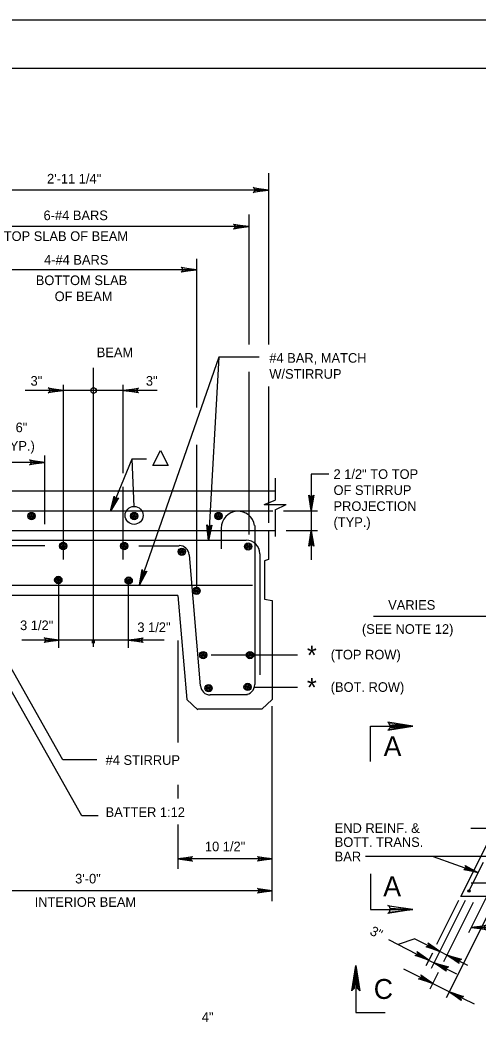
# Model space of a CAD drawing. Extents: x 642009 to 642864, y 298232 to 300014.
# Drawn here: x 642423.1 to 642566, y 299702.6 to 300013.8 of the extents above; entities that cross this region are included whole.
import ezdxf

# ---------------------------------------------------------------- set-up
doc = ezdxf.new("R2010")
doc.units = 0
for name, color, linetype in [('1', 7, 'Continuous'), ('2', 7, 'Continuous'), ('PLT-BNDY', 7, 'Continuous')]:
    doc.layers.add(name, color=color, linetype=linetype)

msp = doc.modelspace()

# ---------------------------------------------------------------- linework, layer by layer
at = {"layer": '1'}
msp.add_line((642552.01, 299752.72), (642565.95, 299747.74), dxfattribs=at)
for points in [[(642496.11, 299961.31), (642496.28, 299960.98), (642500.65, 299960.74), (642496.11, 299961.31), (642495.87, 299961.51), (642500.65, 299960.74), (642496.28, 299960.52), (642496.12, 299960.2), (642500.65, 299960.74), (642495.87, 299959.98), (642496.12, 299960.2)], [(642489.92, 299949.87), (642490.09, 299949.54), (642494.46, 299949.3), (642489.92, 299949.87), (642489.69, 299950.07), (642494.46, 299949.3), (642490.09, 299949.08), (642489.93, 299948.76), (642494.46, 299949.3), (642489.69, 299948.54), (642489.93, 299948.76)], [(642473.61, 299936.41), (642473.78, 299936.08), (642478.15, 299935.84), (642473.61, 299936.41), (642473.37, 299936.61), (642478.15, 299935.84), (642473.78, 299935.62), (642473.62, 299935.3), (642478.15, 299935.84), (642473.37, 299935.08), (642473.62, 299935.3)], [(642432.17, 299898.75), (642432.34, 299898.43), (642436.71, 299898.18), (642432.17, 299898.75), (642431.94, 299898.95), (642436.71, 299898.18), (642432.34, 299897.97), (642432.18, 299897.64), (642436.71, 299898.18), (642431.94, 299897.43), (642432.18, 299897.64)], [(642459.81, 299897.61), (642459.64, 299897.94), (642455.27, 299898.18), (642459.81, 299897.61), (642460.05, 299897.42), (642455.27, 299898.18), (642459.64, 299898.4), (642459.8, 299898.73), (642455.27, 299898.18), (642460.05, 299898.94), (642459.8, 299898.73)], [(642426.34, 299876.28), (642426.51, 299875.95), (642430.88, 299875.71), (642426.34, 299876.28), (642426.1, 299876.48), (642430.88, 299875.71), (642426.51, 299875.49), (642426.35, 299875.17), (642430.88, 299875.71), (642426.1, 299874.95), (642426.35, 299875.17)], [(642453.6, 299864.47), (642453.23, 299864.44), (642451.36, 299860.48), (642453.6, 299864.47), (642453.87, 299864.61), (642451.36, 299860.48), (642452.81, 299864.61), (642452.57, 299864.88), (642451.36, 299860.48), (642452.46, 299865.19), (642452.57, 299864.88)], [(642514.53, 299865.24), (642514.21, 299865.07), (642513.96, 299860.7), (642514.53, 299865.24), (642514.73, 299865.47), (642513.96, 299860.7), (642513.75, 299865.07), (642513.42, 299865.22), (642513.96, 299860.7), (642513.21, 299865.47), (642513.42, 299865.22)], [(642482.74, 299855.89), (642482.4, 299855.74), (642481.91, 299851.38), (642482.74, 299855.89), (642482.95, 299856.11), (642481.91, 299851.38), (642481.94, 299855.76), (642481.63, 299855.93), (642481.91, 299851.38), (642481.42, 299856.19), (642481.63, 299855.93)], [(642513.39, 299849.85), (642513.72, 299850.02), (642513.96, 299854.39), (642513.39, 299849.85), (642513.2, 299849.61), (642513.96, 299854.39), (642514.18, 299850.02), (642514.51, 299849.86), (642513.96, 299854.39), (642514.72, 299849.61), (642514.51, 299849.86)], [(642462.37, 299841.61), (642462, 299841.56), (642460.33, 299837.51), (642462.37, 299841.61), (642462.63, 299841.77), (642460.33, 299837.51), (642461.57, 299841.71), (642461.31, 299841.97), (642460.33, 299837.51), (642461.19, 299842.27), (642461.31, 299841.97)]]:
    msp.add_lwpolyline(points, dxfattribs=at)
msp.add_lwpolyline([(642464.5, 299874.7), (642466.91, 299879.39), (642469.32, 299874.7)], close=True, dxfattribs=at)
msp.add_circle((642458.7, 299859.18), 2.8, dxfattribs=at)
at = {"layer": '2'}
for p, q in [((642048.66, 299998.82), (642834.66, 299998.82)), ((642500.65, 299965.98), (642500.65, 299912.51)), ((642500.65, 299960.74), (642391.52, 299960.74)), ((642494.46, 299953.06), (642494.46, 299912.51)), ((642494.46, 299949.3), (642397.22, 299949.3)), ((642478.15, 299939.21), (642478.15, 299892.89)), ((642478.15, 299935.84), (642414.02, 299935.84)), ((642485.1, 299908.54), (642460.27, 299837.32)), ((642485.1, 299908.54), (642481.91, 299851.38)), ((642497.67, 299908.54), (642485.1, 299908.54)), ((642446.08, 299818.2), (642446.08, 299905.26)), ((642494.46, 299903.95), (642494.46, 299853.19)), ((642436.71, 299898.18), (642424.75, 299898.18)), ((642436.71, 299845.39), (642436.71, 299899.89)), ((642455.27, 299898.18), (642436.71, 299898.18)), ((642455.27, 299872.33), (642455.27, 299899.89)), ((642465.86, 299898.18), (642455.27, 299898.18)), ((642500.65, 299899.37), (642500.65, 299856.89)), ((642478.15, 299881.18), (642478.15, 299836.39)), ((642430.88, 299875.71), (642416.94, 299875.71)), ((642430.88, 299856.47), (642430.88, 299877.85)), ((642457.94, 299876.74), (642451.36, 299860.48)), ((642462.58, 299876.74), (642457.94, 299876.74)), ((642457.94, 299876.74), (642458.64, 299861.98)), ((642502.67, 299870.76), (642502.67, 299863.94)), ((642502.67, 299869.89), (642502.67, 299867.77)), ((642513.96, 299872), (642513.96, 299860.7)), ((642519.39, 299872), (642513.96, 299872)), ((642502.67, 299866.72), (642387.65, 299866.72)), ((642455.27, 299845.39), (642455.27, 299868.06)), ((642499.29, 299862.54), (642502.67, 299863.94)), ((642501.93, 299860.48), (642391.81, 299860.48)), ((642499.29, 299862.54), (642506.17, 299862.54)), ((642502.67, 299860.87), (642506.17, 299862.54)), ((642502.67, 299860.87), (642502.67, 299852.58)), ((642515.87, 299860.52), (642505.32, 299860.52)), ((642513.96, 299860.7), (642513.96, 299854.39)), ((642502.67, 299858.12), (642502.67, 299855.42)), ((642502.67, 299854.39), (642387.65, 299854.39)), ((642485.89, 299855.23), (642485.89, 299848.72)), ((642496.3, 299855.99), (642496.3, 299806.39)), ((642500.65, 299854.39), (642500.65, 299845.39)), ((642515.87, 299854.39), (642506.12, 299854.39)), ((642513.96, 299854.39), (642513.96, 299845.26)), ((642493.64, 299851.38), (642398.5, 299851.38)), ((642430.88, 299849.71), (642419.25, 299849.71)), ((642460.22, 299849.7), (642472.78, 299849.7)), ((642475.92, 299846.91), (642479.27, 299806.01)), ((642497.89, 299847.21), (642497.89, 299809.39)), ((642500.65, 299845.39), (642499.33, 299845.01)), ((642499.33, 299845.01), (642499.33, 299833.01)), ((642435.21, 299817.82), (642435.21, 299838.45)), ((642456.96, 299817.82), (642456.96, 299838.45)), ((642495.58, 299837.32), (642396.4, 299837.32)), ((642472.33, 299834.14), (642419.83, 299834.14)), ((642472.33, 299834.14), (642475.15, 299801.7)), ((642499.33, 299833.01), (642501.77, 299832.64)), ((642501.77, 299832.64), (642501.77, 299801.7)), ((642533.37, 299827.76), (642571.96, 299827.76)), ((642436.44, 299782.86), (642414.07, 299822.57)), ((642435.21, 299820.26), (642423.66, 299820.26)), ((642446.27, 299820.26), (642435.21, 299820.26)), ((642456.96, 299820.26), (642446.27, 299820.26)), ((642468.06, 299820.26), (642456.94, 299820.26)), ((642472.33, 299820.1), (642472.33, 299788.34)), ((642503.65, 299815.57), (642482.72, 299815.57)), ((642509.65, 299815.57), (642502.52, 299815.57)), ((642442.37, 299765.44), (642417.96, 299808.76)), ((642509.65, 299805.41), (642496.2, 299805.41)), ((642475.15, 299801.7), (642478.52, 299798.51)), ((642494.08, 299803.2), (642482.46, 299803.2)), ((642501.77, 299801.7), (642498.58, 299798.7)), ((642498.58, 299798.7), (642478.52, 299798.7)), ((642501.77, 299788.34), (642501.77, 299799.64)), ((642501.77, 299738.72), (642501.77, 299799.64)), ((642532.45, 299793.4), (642545.66, 299793.4)), ((642532.45, 299782.33), (642532.45, 299793.4)), ((642563.05, 299729.01), (642595.68, 299794.41)), ((642447.03, 299782.86), (642436.44, 299782.86)), ((642560.61, 299740.22), (642581.91, 299782.91)), ((642472.33, 299775.12), (642472.33, 299770.82)), ((642447.45, 299765.44), (642442.37, 299765.44)), ((642472.33, 299762.65), (642472.33, 299748.83)), ((642671.29, 299761.49), (642563.68, 299761.49)), ((642501.77, 299751.95), (642472.33, 299751.95)), ((642577.71, 299752.72), (642530.85, 299752.72)), ((642567.53, 299750.83), (642563.12, 299741.97)), ((642532.45, 299747.26), (642532.45, 299736.19)), ((642501.77, 299742.02), (642390.4, 299742.02)), ((642563.12, 299741.94), (642563.12, 299741.94)), ((642563.12, 299741.94), (642563.12, 299741.94)), ((642563.12, 299741.94), (642563.12, 299741.94)), ((642563.12, 299741.94), (642563.12, 299741.94)), ((642563.12, 299741.94), (642563.12, 299741.94)), ((642563.12, 299741.94), (642563.12, 299741.94)), ((642563.12, 299741.94), (642563.12, 299741.94)), ((642563.12, 299741.94), (642563.12, 299741.94)), ((642563.12, 299741.94), (642563.12, 299741.94)), ((642563.12, 299741.94), (642563.12, 299741.94)), ((642563.12, 299741.94), (642563.12, 299741.94)), ((642563.12, 299741.94), (642563.12, 299741.94)), ((642563.12, 299741.94), (642563.12, 299741.94)), ((642656.06, 299744.39), (642563.78, 299744.39)), ((642551.48, 299717.86), (642562.04, 299739.04)), ((642553.15, 299725.34), (642560.02, 299739.03)), ((642556.13, 299708.73), (642571.21, 299738.82)), ((642656.06, 299740.22), (642560.61, 299740.22)), ((642532.45, 299736.19), (642545.66, 299736.19)), ((642555.33, 299719.97), (642564.52, 299738.41)), ((642563.91, 299730.59), (642578.29, 299730.59)), ((642538.01, 299726.77), (642549.73, 299720.82)), ((642546.23, 299727.04), (642541.01, 299725.24)), ((642546.23, 299727.04), (642553.15, 299723.53)), ((642553.15, 299723.53), (642557.17, 299721.52)), ((642549.73, 299720.82), (642553.75, 299718.81)), ((642549.8, 299718.66), (642551.82, 299722.69)), ((642557.17, 299721.52), (642562.64, 299718.79)), ((642527.83, 299718.66), (642527.83, 299703.99)), ((642542.71, 299717.63), (642551.08, 299713.45)), ((642553.75, 299718.81), (642559.21, 299716.08)), ((642551.04, 299711.36), (642553.65, 299716.59)), ((642551.08, 299713.45), (642557.69, 299710.14)), ((642557.69, 299710.14), (642564.72, 299706.69)), ((642527.83, 299703.99), (642537.03, 299703.99))]:
    msp.add_line(p, q, dxfattribs=at)
for points in [[(642430.85, 299820.81), (642431.01, 299820.49), (642435.21, 299820.26), (642430.85, 299820.81), (642430.63, 299821), (642435.21, 299820.26), (642431.02, 299820.05), (642430.86, 299819.74), (642435.21, 299820.26), (642430.63, 299819.53), (642430.86, 299819.74)], [(642461.3, 299819.71), (642461.14, 299820.03), (642456.94, 299820.26), (642461.3, 299819.71), (642461.52, 299819.52), (642456.94, 299820.26), (642461.13, 299820.47), (642461.29, 299820.78), (642456.94, 299820.26), (642461.52, 299820.99), (642461.29, 299820.78)], [(642538.2, 299792.36), (642538.41, 299792.99), (642545.66, 299793.4), (642538.2, 299792.36), (642537.79, 299792.16), (642545.66, 299793.4), (642538.41, 299793.61), (642538.2, 299794.23), (642545.66, 299793.4), (642537.79, 299794.64), (642538.2, 299794.23)], [(642476.69, 299751.41), (642476.53, 299751.72), (642472.33, 299751.95), (642476.69, 299751.41), (642476.92, 299751.21), (642472.33, 299751.95), (642476.53, 299752.16), (642476.68, 299752.47), (642472.33, 299751.95), (642476.92, 299752.68), (642476.68, 299752.47)], [(642497.41, 299752.5), (642497.57, 299752.18), (642501.77, 299751.95), (642497.41, 299752.5), (642497.19, 299752.69), (642501.77, 299751.95), (642497.58, 299751.75), (642497.42, 299751.43), (642501.77, 299751.95), (642497.19, 299751.22), (642497.42, 299751.43)], [(642562.06, 299749.68), (642562.11, 299749.37), (642565.95, 299747.74), (642562.06, 299749.68), (642561.98, 299749.87), (642565.95, 299747.74), (642561.97, 299748.96), (642561.74, 299748.73), (642565.95, 299747.74), (642561.51, 299748.51), (642561.74, 299748.73)], [(642497.41, 299742.57), (642497.57, 299742.26), (642501.77, 299742.02), (642497.41, 299742.57), (642497.19, 299742.76), (642501.77, 299742.02), (642497.58, 299741.82), (642497.42, 299741.5), (642501.77, 299742.02), (642497.19, 299741.3), (642497.42, 299741.5)], [(642538.2, 299737.23), (642538.41, 299736.61), (642545.66, 299736.19), (642538.2, 299737.23), (642537.79, 299737.44), (642545.66, 299736.19), (642538.41, 299735.99), (642538.2, 299735.37), (642545.66, 299736.19), (642537.79, 299734.95), (642538.2, 299735.37)], [(642568.23, 299730.01), (642568.08, 299730.3), (642563.91, 299730.59), (642568.23, 299730.01), (642568.51, 299729.87), (642563.91, 299730.59), (642568.08, 299730.73), (642568.23, 299731.02), (642563.91, 299730.59), (642568.51, 299731.31), (642568.23, 299731.02)], [(642547.06, 299722.8), (642547.06, 299722.51), (642550.65, 299720.36), (642547.06, 299722.8), (642546.91, 299723.09), (642550.65, 299720.36), (642546.91, 299722.08), (642546.63, 299721.94), (642550.65, 299720.36), (642546.34, 299721.8), (642546.63, 299721.94)], [(642550.48, 299725.51), (642550.48, 299725.22), (642554.07, 299723.07), (642550.48, 299725.51), (642550.33, 299725.8), (642554.07, 299723.07), (642550.33, 299724.79), (642550.05, 299724.65), (642554.07, 299723.07), (642549.76, 299724.51), (642550.05, 299724.65)], [(642559.91, 299719.64), (642559.91, 299719.93), (642556.32, 299721.94), (642559.91, 299719.64), (642560.06, 299719.36), (642556.32, 299721.94), (642560.2, 299720.36), (642560.49, 299720.51), (642556.32, 299721.94), (642560.77, 299720.65), (642560.49, 299720.51)], [(642526.8, 299711.21), (642527.42, 299711.62), (642527.83, 299718.66), (642526.8, 299711.21), (642526.59, 299710.79), (642527.83, 299718.66), (642528.25, 299711.62), (642528.66, 299711.21), (642527.83, 299718.66), (642529.07, 299710.79), (642528.66, 299711.21)], [(642555.91, 299717.23), (642555.91, 299717.51), (642552.31, 299719.53), (642555.91, 299717.23), (642556.05, 299716.94), (642552.31, 299719.53), (642556.19, 299717.95), (642556.48, 299718.09), (642552.31, 299719.53), (642556.77, 299718.23), (642556.48, 299718.09)], [(642548.23, 299715.52), (642548.23, 299715.23), (642551.83, 299713.07), (642548.23, 299715.52), (642548.09, 299715.81), (642551.83, 299713.07), (642547.95, 299714.8), (642547.8, 299714.51), (642551.83, 299713.07), (642547.37, 299714.51), (642547.8, 299714.51)], [(642560.74, 299708.04), (642560.6, 299708.47), (642557.01, 299710.48), (642560.74, 299708.04), (642560.74, 299707.75), (642557.01, 299710.48), (642560.89, 299708.76), (642561.18, 299709.05), (642557.01, 299710.48), (642561.46, 299709.05), (642561.18, 299709.05)]]:
    msp.add_lwpolyline(points, dxfattribs=at)
for centre, radius in [((642446.05, 299898.17), 0.86), ((642426.71, 299858.98), 1.14), ((642458.7, 299858.98), 1.14), ((642485.02, 299858.98), 1.14), ((642426.71, 299858.98), 0.817), ((642426.71, 299858.98), 0.447), ((642426.71, 299858.98), 0.225), ((642426.71, 299858.98), 0.0966), ((642458.7, 299858.98), 0.817), ((642458.7, 299858.98), 0.447), ((642458.7, 299858.98), 0.225), ((642458.7, 299858.98), 0.0966), ((642485.02, 299858.98), 0.817), ((642485.02, 299858.98), 0.447), ((642485.02, 299858.98), 0.225), ((642485.02, 299858.98), 0.0966), ((642436.56, 299849.62), 1.14), ((642455.61, 299849.62), 1.14), ((642494.24, 299849.46), 1.14), ((642436.56, 299849.62), 0.817), ((642436.56, 299849.62), 0.447), ((642436.56, 299849.62), 0.225), ((642436.56, 299849.62), 0.0966), ((642455.61, 299849.62), 0.817), ((642455.61, 299849.62), 0.447), ((642455.61, 299849.62), 0.225), ((642455.61, 299849.62), 0.0966), ((642473.57, 299847.83), 1.14), ((642473.57, 299847.83), 0.817), ((642473.57, 299847.83), 0.447), ((642473.57, 299847.83), 0.225), ((642473.57, 299847.83), 0.0966), ((642494.24, 299849.46), 0.817), ((642494.24, 299849.46), 0.447), ((642494.24, 299849.46), 0.225), ((642494.24, 299849.46), 0.0966), ((642435.06, 299839.02), 1.14), ((642435.06, 299839.02), 0.817), ((642435.06, 299839.02), 0.447), ((642435.06, 299839.02), 0.225), ((642435.06, 299839.02), 0.0966), ((642457, 299838.83), 1.14), ((642457, 299838.83), 0.817), ((642457, 299838.83), 0.447), ((642457, 299838.83), 0.225), ((642457, 299838.83), 0.0966), ((642478.18, 299835.64), 1.14), ((642478.18, 299835.64), 0.817), ((642478.18, 299835.64), 0.447), ((642478.18, 299835.64), 0.225), ((642478.18, 299835.64), 0.0966), ((642480.25, 299815.58), 1.14), ((642480.25, 299815.58), 0.817), ((642494.84, 299815.58), 1.14), ((642494.84, 299815.58), 0.817), ((642480.25, 299815.58), 0.447), ((642480.25, 299815.58), 0.225), ((642480.25, 299815.58), 0.0966), ((642494.84, 299815.58), 0.447), ((642494.84, 299815.58), 0.225), ((642494.84, 299815.58), 0.0966), ((642481.93, 299805.27), 1.14), ((642481.93, 299805.27), 0.817), ((642481.93, 299805.27), 0.447), ((642481.93, 299805.27), 0.225), ((642481.93, 299805.27), 0.0966), ((642494.09, 299805.64), 1.14), ((642494.09, 299805.64), 0.817), ((642494.09, 299805.64), 0.447), ((642494.09, 299805.64), 0.225), ((642494.09, 299805.64), 0.0966), ((642563.12, 299741.97), 0.356), ((642563.12, 299741.97), 0.197), ((642563.12, 299741.97), 0.0936)]:
    msp.add_circle(centre, radius, dxfattribs=at)
for centre, radius, start, end in [((642491.12, 299855.23), 5.23, 8.3783, 180), ((642493.64, 299847.21), 4.25, 0, 90), ((642472.74, 299846.65), 3.09, 4.7619, 90), ((642482.45, 299806.25), 3.09, 184.7608, 270), ((642493.23, 299806.37), 3.09, 270, 0)]:
    msp.add_arc(centre, radius, start, end, dxfattribs=at)
at = {"layer": 'PLT-BNDY'}
msp.add_lwpolyline([(642008.66, 300013.82), (642849.66, 300013.82), (642849.66, 299419.82), (642008.66, 299419.82)], close=True, dxfattribs=at)

# ---------------------------------------------------------------- texts
at = {"layer": '2'}
for s, height, p in [('2\'-11 1/4"', 3, (642431.53, 299962.77)), ('6-#4 BARS', 3, (642430.45, 299951.33)), ('TOP SLAB OF BEAM', 3, (642418.03, 299944.84)), ('4-#4 BARS', 3, (642430.61, 299937.45)), ('BOTTOM SLAB', 3, (642428.03, 299931.06)), ('OF BEAM', 3, (642433.91, 299926.06)), ('  BEAM', 3, (642444.81, 299908.56)), ('#4 BAR, MATCH', 3, (642500.87, 299906.83)), ('W/STIRRUP', 3, (642500.87, 299901.83)), ('3"', 3, (642426.4, 299899.67)), ('3"', 3, (642462.37, 299899.67)), ('6"', 3, (642421.74, 299885.14)), ('(TYP.)', 3, (642416.14, 299879.38)), ('2 1/2" TO TOP', 3, (642520.89, 299870.57)), ('OF STIRRUP', 3, (642520.89, 299865.57)), ('PROJECTION', 3, (642520.89, 299860.57)), ('(TYP.)', 3, (642520.89, 299855.57)), ('VARIES', 3, (642537.93, 299829.73)), ('3 1/2"', 3, (642423.13, 299823.37)), ('3 1/2"', 3, (642459.71, 299822.76)), ('(SEE NOTE 12)', 2.9998, (642529.75, 299822.21)), ('*', 5.88, (642512.6, 299812.63)), ('(TOP ROW)', 3, (642520.02, 299814.23)), ('*', 5.88, (642512.6, 299802.57)), ('(BOT. ROW)', 3, (642520.01, 299804.1)), ('A', 6.21, (642536.53, 299784.04)), ('#4 STIRRUP', 3, (642449.82, 299781.31)), ('BATTER 1:12', 3, (642449.8, 299765.06)), ('END REINF. &', 2.9998, (642521.26, 299760.08)), ('10 1/2"', 3, (642480.78, 299754.35)), ('BOTT. TRANS. ', 2.9998, (642521.26, 299755.71)), ('BAR', 3, (642521.26, 299751.21)), ('3\'-0"', 3, (642440.31, 299744.3)), ('A', 6.21, (642536.41, 299740.32)), ('INTERIOR BEAM', 3, (642427.68, 299737)), ('C', 6.21, (642533.44, 299708.26)), ('4"', 3, (642479.8, 299701.09))]:
    msp.add_text(s, height=height, dxfattribs=at).set_placement(p)
for s, height, rotation, p in [('.', 6.68, 270, (642445.41, 299820.88)), ('3"', 3, 333.4537, (642531.96, 299728.46))]:
    msp.add_text(s, height=height, rotation=rotation, dxfattribs=at).set_placement(p)

doc.saveas('drawing.dxf')
